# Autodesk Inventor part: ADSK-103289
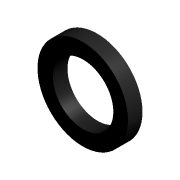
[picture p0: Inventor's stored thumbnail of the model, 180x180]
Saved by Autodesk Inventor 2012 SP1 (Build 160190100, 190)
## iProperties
Shininess: 0.0
Created: 2000-04
Part Number: ADSK-103289
Document SubType Name: Modeling
Stock Number: ADSK-103289
Density: 1 g/cm^3
Material: Default
Density: 0.0
Volumn: 0.0
Area: 0.0
PropertySet Name: Model Information
Control State: 0
Checked Out: False
Master: False
Author: gao
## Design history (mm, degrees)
node "Extrusion1" dims "d2" = 23.99792, "d3" = 0
  sketch "Sketch1"
    geometry: C1 r 50 at (-5.725, 0); C2 r 75 at (-6.393, 0)
    constraints: 2 centre point
    dimensions: "d0" = 99.9998 diameter of C1; "d1" = 149.9997 diameter of C2
body "Solid1"
